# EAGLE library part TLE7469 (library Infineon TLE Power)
Infineon TLE 7469 -Dual output 5 V (±2%), 320mA and 2.6 V1) (±4%), 300mA or 5 V (±2%), 320mA and 3.3 V (±3%), 300mA -Ultra low quiescent current consumption < 55 µA- Inhibit function -Very low dropout voltage -Reset with power-on delay -Early Warning comparator -Window watchdog -Power sequencing for dual voltage µC -Output protected against short circuit -Wide operation range: up to 45 V -Wide temperature range: -40 °C to 150 °C -Overtemperature protection -Overload protection Functional Description The TLE 7469 is a monolithic integrated voltage regulator with two voltage outputs specially designed to supply microcontrollers with dual supply voltage: 2.6 V1) or 3.3 V core and 5 V I/O voltage like the Infineon XC164 and XC161. ------------------------------------------ 1)2.5 V nominal specification range of most µCs is compatible with the 2.6 V output voltage range of the TLE 7469. ------------------------------------------ Type Ordering Code Package TLE 7469 GV52 Q67007-A9689 P-DSO-12-4 TLE 7469 GV53 Q67007-A9690 P-DSO-12-4
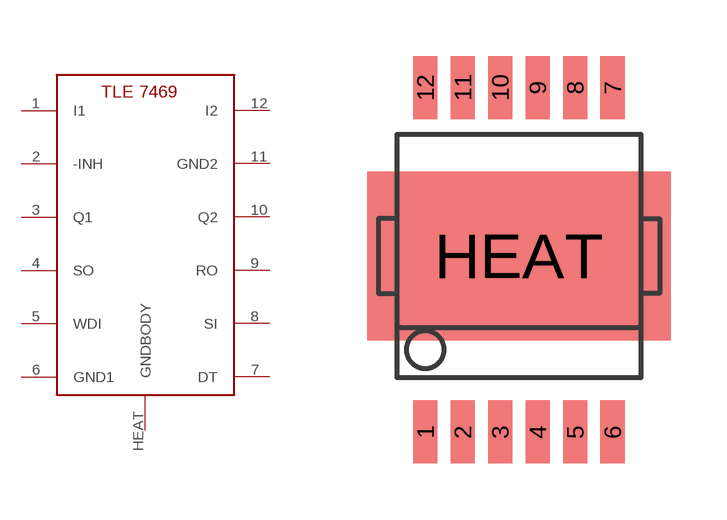
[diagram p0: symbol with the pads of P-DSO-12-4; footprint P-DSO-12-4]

Designator prefix -

## TLE7469GV53  [P-DSO-12-4]
1  I1  in
2  -INH  in
3  Q1  pwr
4  SO  oc
5  WDI  in
6  GND1  pwr
7  DT
8  SI  in
9  RO  out
10  Q2  pwr
11  GND2  pwr
12  I2  in
HEAT  GNDBODY  pwr

## Footprint P-DSO-12-4 (pad centres in mm)
smd 0.65 x 1.676: 1 -2.5,-4.7; 2 -1.5,-4.7; 3 -0.5,-4.7; 4 0.5,-4.7; 5 1.5,-4.7; 6 2.5,-4.7; 7 2.5,4.5; 8 1.5,4.5; 9 0.5,4.5; 10 -0.5,4.5; 11 -1.5,4.5; 12 -2.5,4.5
smd 8.1 x 4.5: HEAT 0,0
